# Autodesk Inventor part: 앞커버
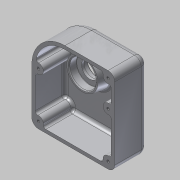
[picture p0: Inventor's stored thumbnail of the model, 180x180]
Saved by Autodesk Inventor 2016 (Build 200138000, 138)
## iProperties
Created: 2015-10
Part Number: 앞커버
Material: 알루미늄 6061
Document SubType Name: Modeling
Designer: mduedu
Density: 2.71 g/cm^3
Mass: 307.08 g
Surface Area: 494.818 cm^2
Volume: 113.314 cm^3
Appearance: 알루미늄 - 평지
Author: mduedu
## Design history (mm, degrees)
sketch "스케치1"
  geometry: L1 (0, 40)-(60, 40); L2 (60, 40)-(60, -63); L3 (60, -63)-(-40, -63); L4 (-40, -63)-(-40, 0); A1 r 40 centre (0, 0) between (0, 40) and (-40, 0); 1 further point
  constraints: 8 end point, 2 point on circle, 2 tangent, 1 centre point, 1 coincident, 1 horizontal, 1 parallel, 1 perpendicular, 1 vertical
  dimensions: "d0" = 40 radius of A1; "d1" = 103 distance of L1.end L2.end; "d2" = 100 distance of L2.end L3.end
extrude "돌출2" new body sketch "스케치1" distance "d8" = 40; taper "d9" = 0 deg
fillet "모깎기3" dims "d10" = 8
fillet "모깎기4" dims "d11" = 8
feature "쉘2" dims "d12" = 4
sketch "스케치2"
  geometry: C1 r 21.5 at (32, 55); 1 further point
  constraints: 1 centre point, 1 coincident
  dimensions: "d13" = 43 diameter of C1
extrude "돌출3" join sketch "스케치2" distance "d14" = 15; taper "d15" = 0 deg
hole "구멍1" diameter "d18" = 32; stored, may be unused: countersink angle "d22" = 90 deg, drill point angle "d24" = 0 deg; dims "d16" = 10, "d17" = 10, "d19" = 6, "d20" = 4, "d21" = 2, "d23" = 9
hole "구멍2" diameter "d27" = 20; stored, may be unused: countersink angle "d31" = 90 deg, drill point angle "d33" = 0 deg; dims "d25" = 10, "d26" = 10, "d28" = 6, "d29" = 4, "d30" = 2, "d32" = 3
hole "구멍3" diameter "d36" = 25; stored, may be unused: countersink angle "d40" = 90 deg, drill point angle "d42" = 0 deg; dims "d34" = 10, "d35" = 10, "d37" = 6, "d38" = 4, "d39" = 2, "d41" = 3
chamfer "모따기1" distance "d43" = 1; stored, may be unused: second distance "d44" = 2, angle "d45" = 45 deg
feature "면 기울기1" dims angle "d46" = 10 deg
sketch "스케치3"
  geometry: L1 (-40, 0)-(-40, -55) reference; L2 (60, -55)-(60, 32) reference; L3 (-40, 0)-(60, 0); C1 r 6 at (52, 32); C2 r 6 at (52, -55); C3 r 6 at (-32, -55); C4 r 6 at (52, 0); C5 r 6 at (-32, 0); A1 r 8 centre (52, 32) between (60, 32) and (52, 40) reference; A2 r 8 centre (52, -55) between (52, -63) and (60, -55) reference; A3 r 8 centre (-32, -55) between (-40, -55) and (-32, -63) reference; 1 further point
  constraints: 5 centre point, 4 equal radius, 3 coincident, 3 point on line, 2 end point, 2 vertical alignment, 1 perpendicular
  dimensions: "d47" = 6 radius of C1
extrude "돌출4" join sketch "스케치3" stored distance "d49" = 15; taper "d50" = 0 deg
fillet "모깎기5" dims "d51" = 3
fillet "모깎기6" dims "d52" = 3
sketch "스케치4"
  geometry: A1 r 6 centre (-32, 0) between (-32.667, -5.963) and (-31.833, 5.998) reference; A2 r 6 centre (52, 32) between (46.037, 32.667) and (52.667, 26.037) reference; A3 r 6 centre (52, 0) between (52.667, 5.963) and (52.667, -5.963) reference; A4 r 6 centre (52, -55) between (52.667, -49.037) and (46.037, -55.667) reference; A5 r 6 centre (-32, -55) between (-26.037, -55.667) and (-32.667, -49.037) reference; 6 further points
  constraints: 5 coincident
hole "구멍4" sketch "스케치4" at (-32, 0), (52, 32), (52, 0), (52, -55), (-32, -55) diameter "d53" = 3.242; stored, may be unused: countersink angle "d57" = 90 deg, drill point angle "d59" = 118 deg; dims "d54" = 12, "d55" = 4, "d56" = 2, "d58" = 14
sketch "스케치5"
  geometry: L1 (-52, -63)-(32, -63) reference; L2 (-60, 32)-(-60, -55) reference; 2 further points
  constraints: 1 other
  dimensions: "d60" = 20 distance from line of point (-10, -43) L1; "d61" = 50 distance from line of point (-10, -43) L2
feature "엠보싱1" sketch "스케치5" dims "d13" = 43, "d62" = 0.5, "d63" = 0
fillet "모깎기7" dims "d64" = 0.3
node "솔리드2"
